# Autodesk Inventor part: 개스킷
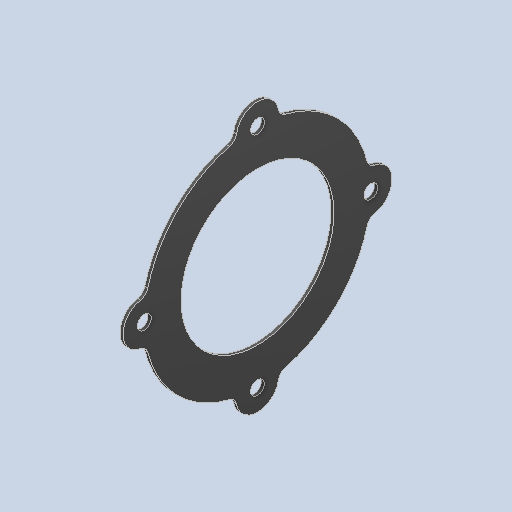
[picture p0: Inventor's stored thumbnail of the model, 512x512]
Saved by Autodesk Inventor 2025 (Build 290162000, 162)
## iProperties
Created: 2024-08
Part Number: 개스킷
Material: 황동, 연질 노란색
Document SubType Name: Modeling
Designer: hsj03
Density: 8.47 g/cm^3
Appearance: 기본값
Author: jhkim
Sending System: Autodesk Inventor 2025
Preprocessor: ST-DEVELOPER v20
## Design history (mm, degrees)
feature "솔리드2"
node "솔리드1"
